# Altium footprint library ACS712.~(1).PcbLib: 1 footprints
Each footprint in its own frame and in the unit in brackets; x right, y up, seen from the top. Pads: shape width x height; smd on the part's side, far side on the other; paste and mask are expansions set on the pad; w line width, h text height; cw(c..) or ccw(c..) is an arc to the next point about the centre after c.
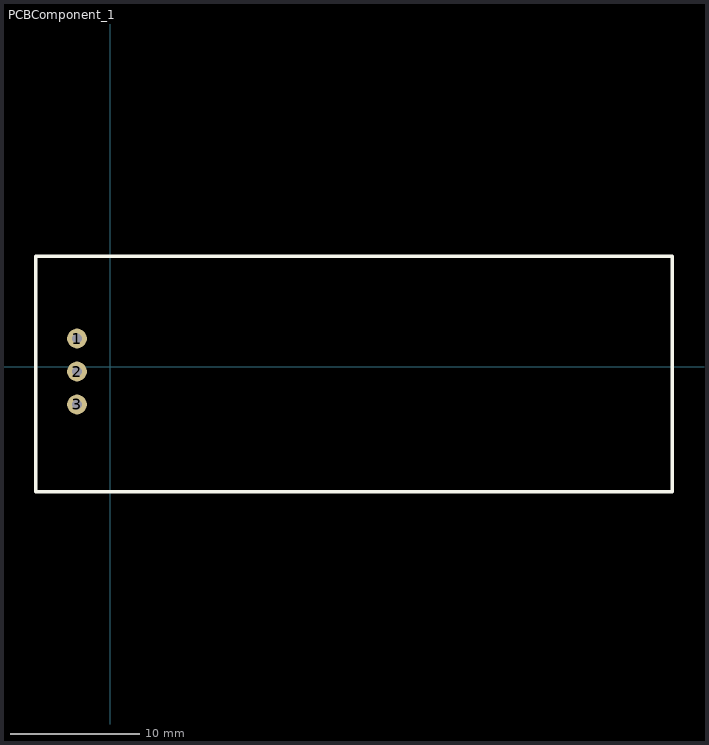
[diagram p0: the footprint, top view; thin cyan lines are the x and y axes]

## PCBComponent_1 [mil]
pads (3):
  round 60 hole 30: 1(-100,85) 2(-100,-15) 3(-100,-115)
Top Overlay:
  lines w10: -225,-380 -225,-15 -225,335 1705,335 1705,-380 -225,-380
3D body: height 787.4, standoff 0, extent -230,-380 1705,335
